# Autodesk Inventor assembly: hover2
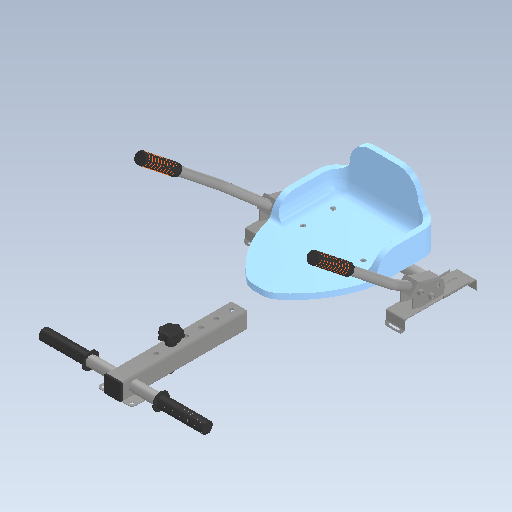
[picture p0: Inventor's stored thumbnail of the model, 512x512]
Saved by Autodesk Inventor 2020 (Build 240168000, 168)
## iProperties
Company: UNSPECIFIED
Created: 1900-01
Part Number: hover2
Description: STEP AP203
Document SubType Name: Assembly
Designer: bruno
Sending System: ASCON Math Kernel
Preprocessor: ASCON STEP Converter 1.3
Title: Òåëåæêà
Author: UNSPECIFIED
Revision Number: ANYUNSPECIFIED
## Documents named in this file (19)
- C:\Users\bruno\Documents\1-Cours-2022-23\1SI\2. Cinématique\Hoverboard\Inventor-Hoverboard\hover2.iam
- C:\Users\bruno\Documents\1-Cours-2022-23\1SI\2. Cinématique\Hoverboard\Inventor-Hoverboard\Tube-2.ipt
- C:\Users\bruno\Documents\1-Cours-2022-23\1SI\2. Cinématique\Hoverboard\Inventor-Hoverboard\Tube-carre.ipt
- C:\Users\bruno\Documents\1-Cours-2022-23\1SI\2. Cinématique\Hoverboard\Inventor-Hoverboard\Plat-1.ipt
- C:\Users\bruno\Documents\1-Cours-2022-23\1SI\2. Cinématique\Hoverboard\Inventor-Hoverboard\Tube-1.ipt
- C:\Users\bruno\Documents\1-Cours-2022-23\1SI\2. Cinématique\Hoverboard\Inventor-Hoverboard\Plat-2.ipt
- C:\Users\bruno\Documents\1-Cours-2022-23\1SI\2. Cinématique\Hoverboard\Inventor-Hoverboard\Ecrou.ipt
- C:\Users\bruno\Documents\1-Cours-2022-23\1SI\2. Cinématique\Hoverboard\Inventor-Hoverboard\Axe-1.iam
- C:\Users\bruno\Documents\1-Cours-2022-23\1SI\2. Cinématique\Hoverboard\Inventor-Hoverboard\Rondelle.ipt
- C:\Users\bruno\Documents\1-Cours-2022-23\1SI\2. Cinématique\Hoverboard\Inventor-Hoverboard\HANDLE GRIP.ipt
- C:\Users\bruno\Documents\1-Cours-2022-23\1SI\2. Cinématique\Hoverboard\Inventor-Hoverboard\Articulation.iam
- C:\Users\bruno\Documents\1-Cours-2022-23\1SI\2. Cinématique\Hoverboard\Inventor-Hoverboard\Rondelle-10450-78.ipt
- C:\Users\bruno\Documents\1-Cours-2022-23\1SI\2. Cinématique\Hoverboard\Inventor-Hoverboard\Poignee-1.iam
- C:\Users\bruno\Downloads\Ðó÷êà_1.iam
- C:\Users\bruno\Downloads\Âèíò ñ öèëèíäðè÷åñêîé ãîëîâêîé è øåñòèãðàííûì óãëóáëåíèåì ïîä êëþ÷ ÃÎÑÒ Ð ÈÑÎ 12474 - Ì8 x 1 x 12.ipt
- C:\Users\bruno\Documents\1-Cours-2022-23\1SI\2. Cinématique\Hoverboard\Inventor-Hoverboard\Screw_Knob.ipt
- C:\Users\bruno\Documents\1-Cours-2022-23\1SI\2. Cinématique\Hoverboard\Inventor-Hoverboard\TUBE CAP 40x40.ipt
- C:\Users\bruno\Documents\1-Cours-2022-23\1SI\2. Cinématique\Hoverboard\Inventor-Hoverboard\TUBE CAP 40x40_1.ipt
- C:\Users\bruno\Downloads\Ñèäåíèå.ipt
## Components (38 placed, 38 different names)
1. 2
2. 3
3. 4
4. 5
5. 6
6. 8
7. 10 [sub-assembly]
8. 11 [sub-assembly]
9. 12
10. 13
11. 14
12. 21 [sub-assembly]
13. 22
14. 23
15. 24
16. 28 [sub-assembly]
17. 29
18. 30 [sub-assembly]
19. 31
20. 32
21. 33
22. 37 [sub-assembly]
23. 38
24. 39
25. 40
26. 41
27. 42
28. 43
29. 44
30. 45
31. 46
32. 47
33. 48
34. 49
35. 50
36. 51
37. 52
38. 53
